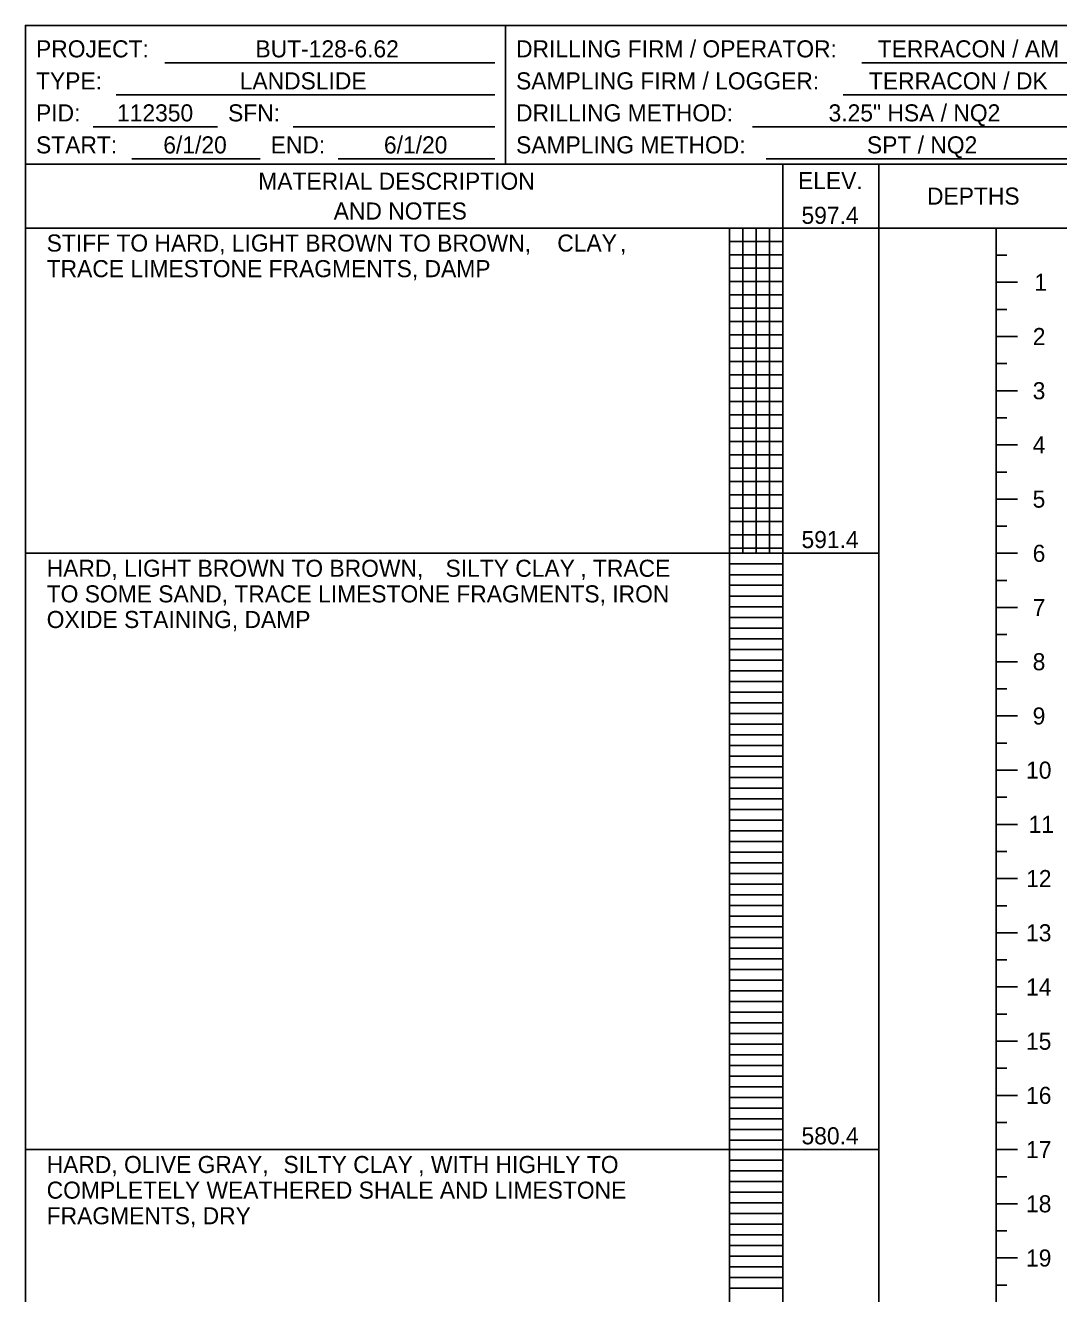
# Model space of a CAD drawing. Extents: x 0 to 0.833, y -0.381 to 0.608.
# Drawn here: x 0 to 0.4036, y 0.1131 to 0.6083 of the extents above; entities that cross this region are included whole.
import ezdxf

# ---------------------------------------------------------------- set-up
doc = ezdxf.new("R2010")
doc.units = 0

msp = doc.modelspace()

# ---------------------------------------------------------------- linework, layer by layer
msp.add_lwpolyline([(0, -0.38086), (0.83333, -0.38086), (0.83333, 0.60833), (0, 0.60833)], close=True)
for points in [[(0.1875, 0.55417), (0.1875, 0.60833)], [(0.05444, 0.59375), (0.18333, 0.59375)], [(0.32667, 0.59375), (0.4125, 0.59375)], [(0.03542, 0.58125), (0.18333, 0.58125)], [(0.31944, 0.58125), (0.4125, 0.58125)], [(0.02653, 0.56875), (0.075, 0.56875)], [(0.10458, 0.56875), (0.18333, 0.56875)], [(0.28403, 0.56875), (0.4125, 0.56875)], [(0.04153, 0.55625), (0.09167, 0.55625)], [(0.12222, 0.55625), (0.18333, 0.55625)], [(0.2893, 0.55625), (0.4125, 0.55625)], [(0, 0.55417), (0.83333, 0.55417)], [(0, 0.55417), (0.83333, 0.55417)], [(0, 0.55417), (0.83333, 0.55417)], [(0, 0.55417), (0.83333, 0.55417)], [(0, 0.55417), (0.83333, 0.55417)], [(0.29583, 0.55417), (0.29583, -0.33867)], [(0.29583, 0.55417), (0.29583, -0.33867)], [(0.33333, 0.55417), (0.33333, -0.33867)], [(0.33333, 0.55417), (0.33333, -0.33867)], [(0, 0.52917), (0.83333, 0.52917)], [(0, 0.52917), (0.83333, 0.52917)], [(0, 0.52917), (0.83333, 0.52917)], [(0, 0.52917), (0.83333, 0.52917)], [(0, 0.52917), (0.83333, 0.52917)], [(0.275, 0.52917), (0.29583, 0.52917)], [(0.275, 0.40217), (0.275, 0.52917)], [(0.275, 0.52917), (0.275, 0.40217)], [(0.275, 0.52917), (0.275, -0.33867)], [(0.28021, 0.40217), (0.28021, 0.52917)], [(0.28542, 0.40217), (0.28542, 0.52917)], [(0.29062, 0.40217), (0.29062, 0.52917)], [(0.29583, 0.40217), (0.29583, 0.52917)], [(0.29583, 0.52917), (0.33333, 0.52917)], [(0.37917, 0.52917), (0.37917, -0.33867)], [(0.275, 0.52396), (0.29583, 0.52396)], [(0.275, 0.51875), (0.29583, 0.51875)], [(0.37917, 0.51858), (0.38333, 0.51858)], [(0.275, 0.51354), (0.29583, 0.51354)], [(0.275, 0.50833), (0.29583, 0.50833)], [(0.37917, 0.508), (0.3875, 0.508)], [(0.37917, 0.508), (0.38333, 0.508)], [(0.275, 0.50312), (0.29583, 0.50312)], [(0.275, 0.49792), (0.29583, 0.49792)], [(0.37917, 0.49742), (0.38333, 0.49742)], [(0.275, 0.49271), (0.29583, 0.49271)], [(0.275, 0.4875), (0.29583, 0.4875)], [(0.37917, 0.48683), (0.3875, 0.48683)], [(0.37917, 0.48683), (0.38333, 0.48683)], [(0.275, 0.48229), (0.29583, 0.48229)], [(0.275, 0.47708), (0.29583, 0.47708)], [(0.37917, 0.47625), (0.38333, 0.47625)], [(0.275, 0.47187), (0.29583, 0.47187)], [(0.275, 0.46667), (0.29583, 0.46667)], [(0.37917, 0.46567), (0.3875, 0.46567)], [(0.37917, 0.46567), (0.38333, 0.46567)], [(0.275, 0.46146), (0.29583, 0.46146)], [(0.275, 0.45625), (0.29583, 0.45625)], [(0.275, 0.45104), (0.29583, 0.45104)], [(0.37917, 0.45508), (0.38333, 0.45508)], [(0.275, 0.44583), (0.29583, 0.44583)], [(0.37917, 0.4445), (0.3875, 0.4445)], [(0.37917, 0.4445), (0.38333, 0.4445)], [(0.275, 0.44062), (0.29583, 0.44062)], [(0.275, 0.43542), (0.29583, 0.43542)], [(0.37917, 0.43392), (0.38333, 0.43392)], [(0.275, 0.43021), (0.29583, 0.43021)], [(0.275, 0.425), (0.29583, 0.425)], [(0.37917, 0.42333), (0.3875, 0.42333)], [(0.37917, 0.42333), (0.38333, 0.42333)], [(0.275, 0.41979), (0.29583, 0.41979)], [(0.275, 0.41458), (0.29583, 0.41458)], [(0.37917, 0.41275), (0.38333, 0.41275)], [(0.275, 0.40937), (0.29583, 0.40937)], [(0, 0.40217), (0.275, 0.40217)], [(0.275, 0.40417), (0.29583, 0.40417)], [(0.275, 0.40217), (0.29583, 0.40217)], [(0.275, 0.40217), (0.29583, 0.40217)], [(0.275, 0.40217), (0.275, 0.16933)], [(0.29583, 0.40217), (0.33333, 0.40217)], [(0.37917, 0.40217), (0.3875, 0.40217)], [(0.37917, 0.40217), (0.38333, 0.40217)], [(0.275, 0.398), (0.29583, 0.398)], [(0.275, 0.39383), (0.29583, 0.39383)], [(0.37917, 0.39158), (0.38333, 0.39158)], [(0.275, 0.38967), (0.29583, 0.38967)], [(0.275, 0.3855), (0.29583, 0.3855)], [(0.275, 0.38133), (0.29583, 0.38133)], [(0.275, 0.37717), (0.29583, 0.37717)], [(0.37917, 0.381), (0.3875, 0.381)], [(0.37917, 0.381), (0.38333, 0.381)], [(0.275, 0.373), (0.29583, 0.373)], [(0.275, 0.36883), (0.29583, 0.36883)], [(0.37917, 0.37042), (0.38333, 0.37042)], [(0.275, 0.36467), (0.29583, 0.36467)], [(0.275, 0.3605), (0.29583, 0.3605)], [(0.37917, 0.35983), (0.3875, 0.35983)], [(0.37917, 0.35983), (0.38333, 0.35983)], [(0.275, 0.35633), (0.29583, 0.35633)], [(0.275, 0.35217), (0.29583, 0.35217)], [(0.275, 0.348), (0.29583, 0.348)], [(0.37917, 0.34925), (0.38333, 0.34925)], [(0.275, 0.34383), (0.29583, 0.34383)], [(0.275, 0.33967), (0.29583, 0.33967)], [(0.37917, 0.33867), (0.3875, 0.33867)], [(0.37917, 0.33867), (0.38333, 0.33867)], [(0.275, 0.3355), (0.29583, 0.3355)], [(0.275, 0.33133), (0.29583, 0.33133)], [(0.275, 0.32717), (0.29583, 0.32717)], [(0.37917, 0.32808), (0.38333, 0.32808)], [(0.275, 0.323), (0.29583, 0.323)], [(0.275, 0.31883), (0.29583, 0.31883)], [(0.37917, 0.3175), (0.3875, 0.3175)], [(0.37917, 0.3175), (0.38333, 0.3175)], [(0.275, 0.31467), (0.29583, 0.31467)], [(0.275, 0.3105), (0.29583, 0.3105)], [(0.275, 0.30633), (0.29583, 0.30633)], [(0.275, 0.30217), (0.29583, 0.30217)], [(0.37917, 0.30692), (0.38333, 0.30692)], [(0.275, 0.298), (0.29583, 0.298)], [(0.275, 0.29383), (0.29583, 0.29383)], [(0.37917, 0.29633), (0.3875, 0.29633)], [(0.37917, 0.29633), (0.38333, 0.29633)], [(0.275, 0.28967), (0.29583, 0.28967)], [(0.275, 0.2855), (0.29583, 0.2855)], [(0.37917, 0.28575), (0.38333, 0.28575)], [(0.275, 0.28133), (0.29583, 0.28133)], [(0.275, 0.27717), (0.29583, 0.27717)], [(0.275, 0.273), (0.29583, 0.273)], [(0.37917, 0.27517), (0.3875, 0.27517)], [(0.37917, 0.27517), (0.38333, 0.27517)], [(0.275, 0.26883), (0.29583, 0.26883)], [(0.275, 0.26467), (0.29583, 0.26467)], [(0.37917, 0.26458), (0.38333, 0.26458)], [(0.275, 0.2605), (0.29583, 0.2605)], [(0.275, 0.25633), (0.29583, 0.25633)], [(0.37917, 0.254), (0.3875, 0.254)], [(0.37917, 0.254), (0.38333, 0.254)], [(0.275, 0.25217), (0.29583, 0.25217)], [(0.275, 0.248), (0.29583, 0.248)], [(0.275, 0.24383), (0.29583, 0.24383)], [(0.37917, 0.24342), (0.38333, 0.24342)], [(0.275, 0.23967), (0.29583, 0.23967)], [(0.275, 0.2355), (0.29583, 0.2355)], [(0.37917, 0.23283), (0.3875, 0.23283)], [(0.37917, 0.23283), (0.38333, 0.23283)], [(0.275, 0.23133), (0.29583, 0.23133)], [(0.275, 0.22717), (0.29583, 0.22717)], [(0.275, 0.223), (0.29583, 0.223)], [(0.275, 0.21883), (0.29583, 0.21883)], [(0.37917, 0.22225), (0.38333, 0.22225)], [(0.275, 0.21467), (0.29583, 0.21467)], [(0.275, 0.2105), (0.29583, 0.2105)], [(0.37917, 0.21167), (0.3875, 0.21167)], [(0.37917, 0.21167), (0.38333, 0.21167)], [(0.275, 0.20633), (0.29583, 0.20633)], [(0.275, 0.20217), (0.29583, 0.20217)], [(0.37917, 0.20108), (0.38333, 0.20108)], [(0.275, 0.198), (0.29583, 0.198)], [(0.275, 0.19383), (0.29583, 0.19383)], [(0.275, 0.18967), (0.29583, 0.18967)], [(0.37917, 0.1905), (0.3875, 0.1905)], [(0.37917, 0.1905), (0.38333, 0.1905)], [(0.275, 0.1855), (0.29583, 0.1855)], [(0.275, 0.18133), (0.29583, 0.18133)], [(0.37917, 0.17992), (0.38333, 0.17992)], [(0.275, 0.17717), (0.29583, 0.17717)], [(0, 0.16933), (0.275, 0.16933)], [(0.275, 0.173), (0.29583, 0.173)], [(0.275, 0.16933), (0.29583, 0.16933)], [(0.275, 0.16933), (0.29583, 0.16933)], [(0.275, 0.16933), (0.275, 0.04233)], [(0.29583, 0.16933), (0.33333, 0.16933)], [(0.37917, 0.16933), (0.3875, 0.16933)], [(0.37917, 0.16933), (0.38333, 0.16933)], [(0.275, 0.16517), (0.29583, 0.16517)], [(0.275, 0.161), (0.29583, 0.161)], [(0.37917, 0.15875), (0.38333, 0.15875)], [(0.275, 0.15683), (0.29583, 0.15683)], [(0.275, 0.15267), (0.29583, 0.15267)], [(0.275, 0.1485), (0.29583, 0.1485)], [(0.275, 0.14433), (0.29583, 0.14433)], [(0.37917, 0.14817), (0.3875, 0.14817)], [(0.37917, 0.14817), (0.38333, 0.14817)], [(0.275, 0.14017), (0.29583, 0.14017)], [(0.275, 0.136), (0.29583, 0.136)], [(0.37917, 0.13758), (0.38333, 0.13758)], [(0.275, 0.13183), (0.29583, 0.13183)], [(0.275, 0.12767), (0.29583, 0.12767)], [(0.37917, 0.127), (0.3875, 0.127)], [(0.37917, 0.127), (0.38333, 0.127)], [(0.275, 0.1235), (0.29583, 0.1235)], [(0.275, 0.11933), (0.29583, 0.11933)], [(0.275, 0.11517), (0.29583, 0.11517)], [(0.37917, 0.11642), (0.38333, 0.11642)]]:
    msp.add_lwpolyline(points)

# ---------------------------------------------------------------- texts
for s, height, p in [('PROJECT:', 0.006667, (0.00417, 0.59583)), ('BUT-128-6.62', 0.0066667, (0.08989, 0.59583)), ('DRILLING FIRM / OPERATOR:', 0.0066667, (0.19167, 0.59583)), ('TERRACON / AM', 0.0066667, (0.33293, 0.59583)), ('TYPE:', 0.006667, (0.00417, 0.58333)), ('LANDSLIDE', 0.006667, (0.08374, 0.58333)), ('SAMPLING FIRM / LOGGER:', 0.0066667, (0.19167, 0.58333)), ('TERRACON / DK', 0.0066667, (0.32949, 0.58333)), ('PID:', 0.006667, (0.00417, 0.57083)), ('112350', 0.006667, (0.0358, 0.57083)), ('SFN:', 0.006667, (0.07917, 0.57083)), ('DRILLING METHOD:', 0.0066667, (0.19167, 0.57083)), ('3.25" HSA / NQ2', 0.0066667, (0.31373, 0.57083)), ('START:', 0.006667, (0.00417, 0.55833)), ('6/1/20', 0.006667, (0.05388, 0.55833)), ('END:', 0.006667, (0.09583, 0.55833)), ('6/1/20', 0.006667, (0.14006, 0.55833)), ('SAMPLING METHOD:', 0.0066667, (0.19167, 0.55833)), ('SPT / NQ2', 0.006667, (0.32872, 0.55833)), ('MATERIAL DESCRIPTION', 0.0066667, (0.09097, 0.54417)), ('ELEV.', 0.006667, (0.30179, 0.54437)), ('DEPTHS', 0.006667, (0.35218, 0.53833)), ('AND NOTES', 0.006667, (0.12044, 0.5325)), ('597.4', 0.006667, (0.30316, 0.53083)), ('STIFF TO HARD, LIGHT BROWN TO BROWN, ', 0.0066667, (0.00833, 0.52)), ('CLAY', 0.006667, (0.20776, 0.52)), (',', 0.00667, (0.23227, 0.52)), ('TRACE LIMESTONE FRAGMENTS, DAMP', 0.0066667, (0.00833, 0.51)), ('1', 0.00667, (0.3941, 0.50467)), ('2', 0.00667, (0.39349, 0.4835)), ('3', 0.00667, (0.39345, 0.46233)), ('4', 0.00667, (0.39347, 0.44117)), ('5', 0.00667, (0.39343, 0.42)), ('591.4', 0.006667, (0.30316, 0.40421)), ('6', 0.00667, (0.39345, 0.39883)), ('HARD, LIGHT BROWN TO BROWN, ', 0.0066667, (0.00833, 0.393)), ('SILTY CLAY', 0.006667, (0.16411, 0.393)), (', TRACE', 0.006667, (0.21674, 0.393)), ('TO SOME SAND, TRACE LIMESTONE FRAGMENTS, IRON', 0.0066667, (0.00833, 0.383)), ('7', 0.00667, (0.39345, 0.37767)), ('OXIDE STAINING, DAMP', 0.0066667, (0.00833, 0.373)), ('8', 0.00667, (0.39345, 0.3565)), ('9', 0.00667, (0.39345, 0.33533)), ('10', 0.006667, (0.39088, 0.31417)), ('11', 0.006667, (0.39186, 0.293)), ('12', 0.006667, (0.3909, 0.27183)), ('13', 0.006667, (0.39087, 0.25067)), ('14', 0.006667, (0.39088, 0.2295)), ('15', 0.006667, (0.39084, 0.20833)), ('16', 0.006667, (0.39087, 0.18717)), ('580.4', 0.006667, (0.30316, 0.17138)), ('17', 0.006667, (0.39087, 0.166)), ('HARD, OLIVE GRAY, ', 0.0066667, (0.00833, 0.16017)), ('SILTY CLAY', 0.006667, (0.10081, 0.16017)), (', WITH HIGHLY TO', 0.0066667, (0.15344, 0.16017)), ('COMPLETELY WEATHERED SHALE AND LIMESTONE', 0.0066667, (0.00833, 0.15017)), ('18', 0.006667, (0.39086, 0.14483)), ('FRAGMENTS, DRY', 0.0066667, (0.00833, 0.14017)), ('19', 0.006667, (0.39086, 0.12367))]:
    msp.add_text(s, height=height).set_placement(p)

doc.saveas('drawing.dxf')
